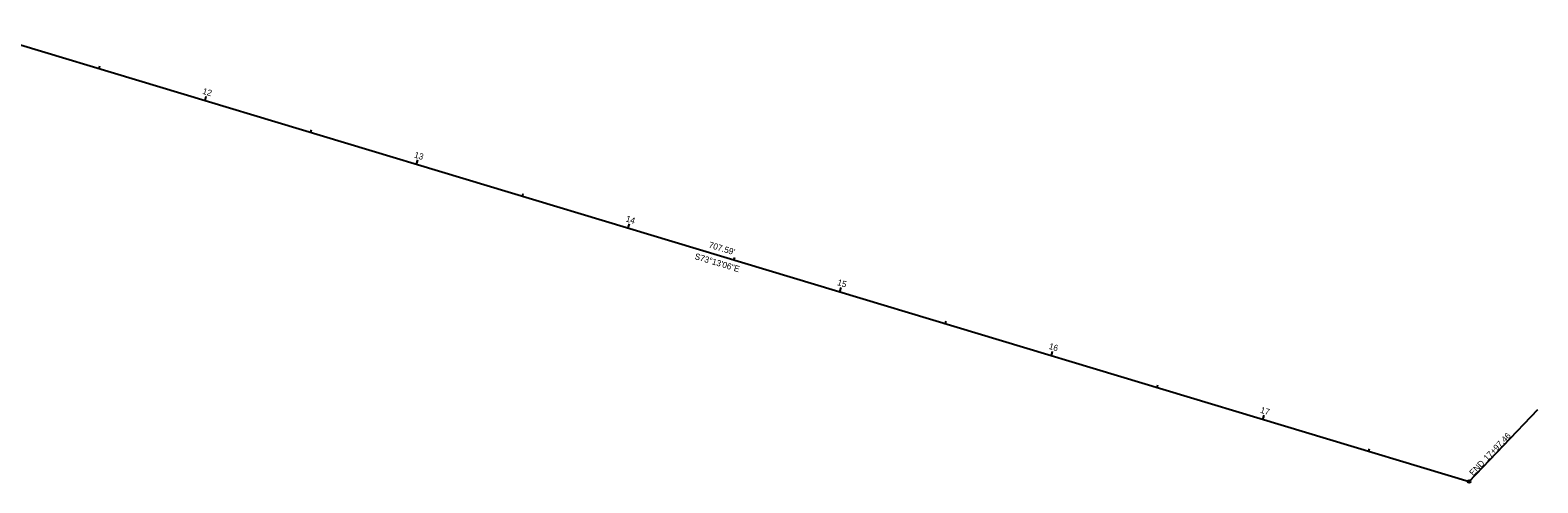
# Model space of a CAD drawing. Extents: x 2196454 to 2197821, y 661371 to 661616.
# Drawn here: x 2197139 to 2197821, y 661371 to 661576 of the extents above; entities that cross this region are included whole.
import ezdxf

# ---------------------------------------------------------------- set-up
doc = ezdxf.new("R2010")
doc.units = 0
for name, color, linetype in [('Default', 7, 'Continuous'), ('GE_X_Alignment', 7, 'Continuous'), ('GE_X_Alignment_1000_Stations', 7, 'Continuous'), ('GE_X_Alignment_100_Stations', 7, 'Continuous'), ('GE_X_Alignment_500_Stations', 7, 'Continuous')]:
    doc.layers.add(name, color=color, linetype=linetype)

msp = doc.modelspace()

# ---------------------------------------------------------------- linework, layer by layer
at = {"layer": 'Default'}
for centre in [(2197218.29, 661544.09), (2197314.04, 661515.22), (2197409.78, 661486.35), (2197451.59, 661473.74), (2197451.59, 661473.74), (2197451.59, 661473.74), (2197451.59, 661473.74), (2197451.59, 661473.74), (2197451.59, 661473.74), (2197505.52, 661457.48), (2197505.52, 661457.48), (2197601.26, 661428.6), (2197697, 661399.73), (2197790.31, 661371.59), (2197790.31, 661371.59), (2197790.31, 661371.59)]:
    msp.add_circle(centre, 0.0000833, dxfattribs=at)
at = {"layer": 'GE_X_Alignment'}
msp.add_line((2197112.86, 661575.89), (2197790.31, 661371.59), dxfattribs=at)
at = {"layer": 'GE_X_Alignment_1000_Stations'}
for p, q in [((2197505.52, 661457.48), (2197505.86, 661458.62)), ((2197790.31, 661371.59), (2197821.4, 661404.12)), ((2197790.31, 661371.59), (2197821.4, 661404.12)), ((2197790.31, 661371.59), (2197821.4, 661404.12)), ((2197790.31, 661371.59), (2197821.4, 661404.12))]:
    msp.add_line(p, q, dxfattribs=at)
msp.add_circle((2197790.31, 661371.59), 0.6, dxfattribs=at)
msp.add_circle((2197790.31, 661371.59), 0.6, dxfattribs=at)
msp.add_circle((2197790.31, 661371.59), 0.6, dxfattribs=at)
msp.add_circle((2197790.31, 661371.59), 0.6, dxfattribs=at)
at = {"layer": 'GE_X_Alignment_100_Stations'}
for p, q in [((2197170.42, 661558.53), (2197170.77, 661559.68)), ((2197218.29, 661544.09), (2197218.87, 661546.01)), ((2197266.16, 661529.66), (2197266.51, 661530.81)), ((2197314.04, 661515.22), (2197314.61, 661517.14)), ((2197361.91, 661500.78), (2197362.25, 661501.93)), ((2197409.78, 661486.35), (2197410.35, 661488.26)), ((2197457.65, 661471.91), (2197457.99, 661473.06)), ((2197505.52, 661457.48), (2197506.1, 661459.39)), ((2197553.39, 661443.04), (2197553.73, 661444.19)), ((2197601.26, 661428.6), (2197601.84, 661430.52)), ((2197649.13, 661414.17), (2197649.48, 661415.32)), ((2197697, 661399.73), (2197697.58, 661401.65)), ((2197790.31, 661371.59), (2197821.4, 661404.12)), ((2197790.31, 661371.59), (2197821.4, 661404.12)), ((2197790.31, 661371.59), (2197821.4, 661404.12)), ((2197790.31, 661371.59), (2197821.4, 661404.12)), ((2197744.87, 661385.29), (2197745.22, 661386.44))]:
    msp.add_line(p, q, dxfattribs=at)
msp.add_circle((2197790.31, 661371.59), 0.6, dxfattribs=at)
msp.add_circle((2197790.31, 661371.59), 0.6, dxfattribs=at)
msp.add_circle((2197790.31, 661371.59), 0.6, dxfattribs=at)
msp.add_circle((2197790.31, 661371.59), 0.6, dxfattribs=at)
at = {"layer": 'GE_X_Alignment_500_Stations'}
for p, q in [((2197218.29, 661544.09), (2197218.64, 661545.24)), ((2197314.04, 661515.22), (2197314.38, 661516.37)), ((2197409.78, 661486.35), (2197410.12, 661487.5)), ((2197505.52, 661457.48), (2197506.1, 661459.39)), ((2197601.26, 661428.6), (2197601.61, 661429.75)), ((2197790.31, 661371.59), (2197821.4, 661404.12)), ((2197790.31, 661371.59), (2197821.4, 661404.12)), ((2197790.31, 661371.59), (2197821.4, 661404.12)), ((2197790.31, 661371.59), (2197821.4, 661404.12)), ((2197697, 661399.73), (2197697.35, 661400.88))]:
    msp.add_line(p, q, dxfattribs=at)
msp.add_circle((2197790.31, 661371.59), 0.6, dxfattribs=at)
msp.add_circle((2197790.31, 661371.59), 0.6, dxfattribs=at)
msp.add_circle((2197790.31, 661371.59), 0.6, dxfattribs=at)
msp.add_circle((2197790.31, 661371.59), 0.6, dxfattribs=at)

# ---------------------------------------------------------------- texts
at = {"layer": 'GE_X_Alignment_1000_Stations'}
for s, rotation, p in [("707.59'", 343.21826, (2197445.96, 661477.53)), ('S73°13\'06"E', 343.21826, (2197439.6, 661472.34)), ('17+97.46', 46.30034, (2197798.57, 661380.71)), ('END', 46.30034, (2197792.12, 661373.95))]:
    msp.add_text(s, height=2.8, rotation=rotation, dxfattribs=at).set_placement(p)
at = {"layer": 'GE_X_Alignment_100_Stations'}
for s, p in [('12', (2197216.92, 661547.12)), ('13', (2197312.69, 661518.29)), ('14', (2197408.44, 661489.36)), ("707.59'", (2197445.96, 661477.53)), ('S73°13\'06"E', (2197439.6, 661472.34)), ('15', (2197504.14, 661460.55)), ('16', (2197599.89, 661431.68)), ('17', (2197695.57, 661402.77))]:
    msp.add_text(s, height=2.8, rotation=343.21826, dxfattribs=at).set_placement(p)
at = {"layer": 'GE_X_Alignment_500_Stations'}
for s, rotation, p in [("707.59'", 343.21826, (2197445.96, 661477.53)), ('S73°13\'06"E', 343.21826, (2197439.6, 661472.34)), ('15', 343.21826, (2197504.14, 661460.55)), ('17+97.46', 46.30034, (2197798.57, 661380.71)), ('END', 46.30034, (2197792.12, 661373.95))]:
    msp.add_text(s, height=2.8, rotation=rotation, dxfattribs=at).set_placement(p)

doc.saveas('drawing.dxf')
